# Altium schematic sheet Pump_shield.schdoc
size A4; Organization: ECAM; Revision: 0; SheetNumber: 1; SheetTotal: 1
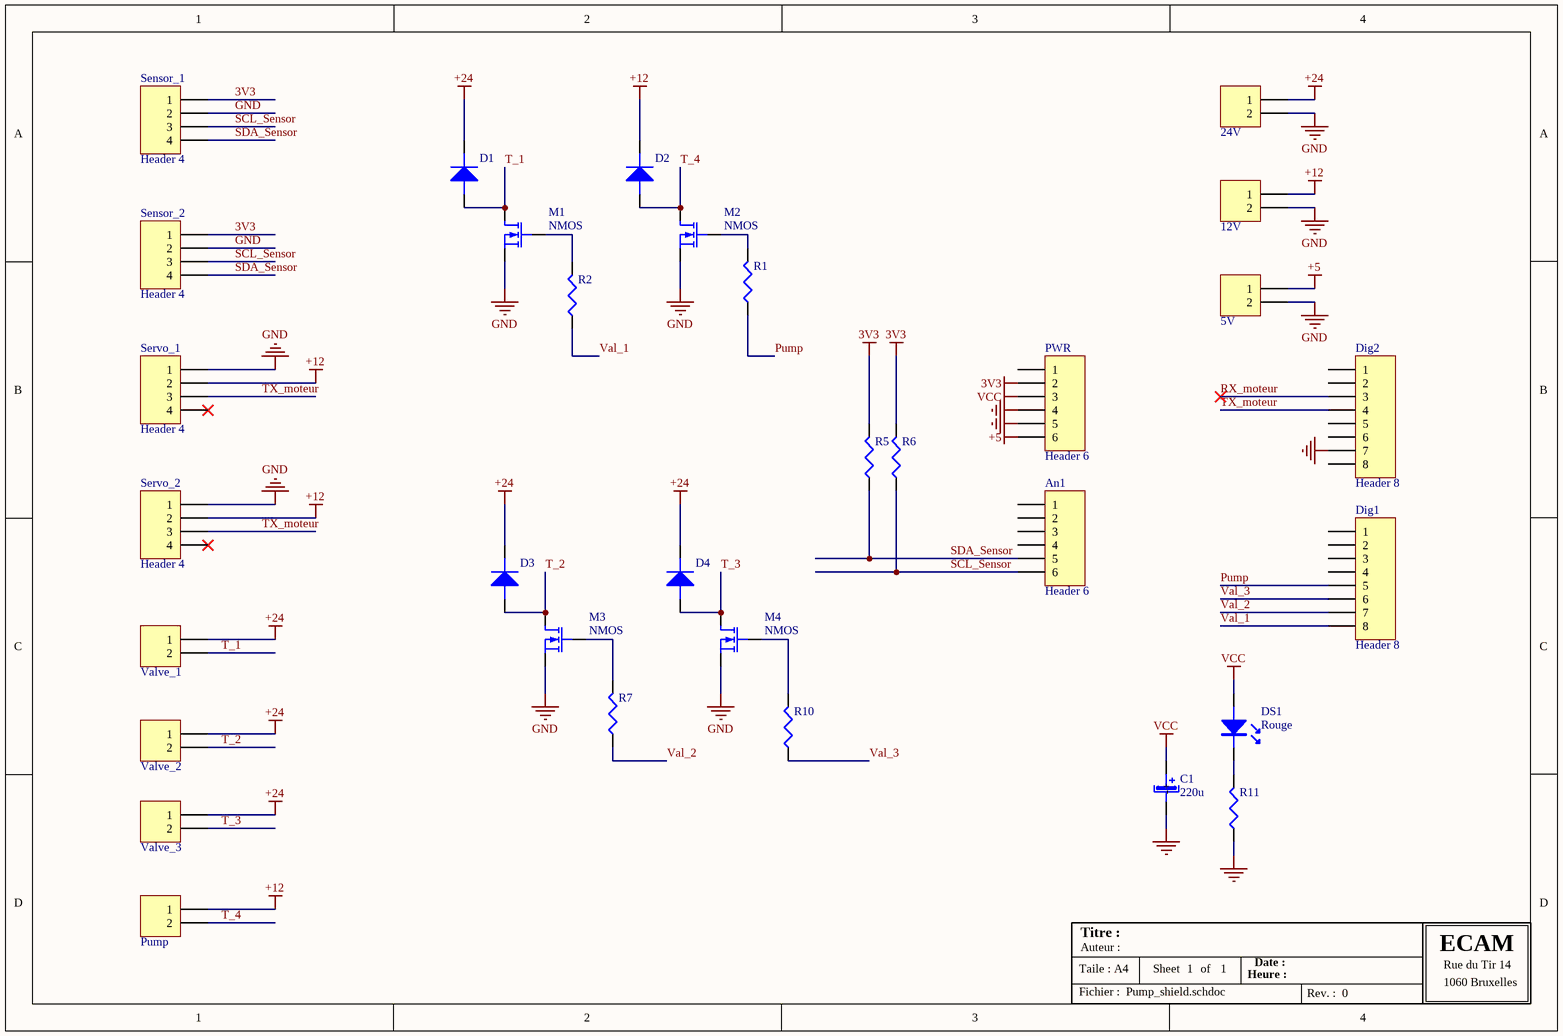
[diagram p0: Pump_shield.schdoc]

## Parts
5V  Connecteur 2  [Header_2]  (value not drawn)
12V  Connecteur 2  [Header_2]  (value not drawn)
24V  Connecteur 2  [Header_2]  (value not drawn)
An1  Header 6  [HDR1X6]
C1  value 220u  [CAPAE0810X700N]  (hidden comment: Cap_220u)
D1  Diode  [DIO7.1-3.9x1.9]  (value not drawn)
D2  Diode  [DIO7.1-3.9x1.9]  (value not drawn)
D3  Diode  [DIO7.1-3.9x1.9]  (value not drawn)
D4  Diode  [DIO7.1-3.9x1.9]  (value not drawn)
Dig1  Header 8  [HDR1X8]
Dig2  Header 8  [HDR1X8]
DS1  Color: Rouge  [LED 0.1]  (hidden comment: LED)
M1  value NMOS  [TO-92bis_MOS-N]  (hidden comment: MOSFET-N)
M2  value NMOS  [TO-220_MOS-N]  (hidden comment: MOSFET-N)
M3  value NMOS  [TO-92bis_MOS-N]  (hidden comment: MOSFET-N)
M4  value NMOS  [TO-92bis_MOS-N]  (hidden comment: MOSFET-N)
Pump  Connecteur 2  [Header_2]  (value not drawn)
PWR  Header 6  [HDR1X6]
R1  Résistance  [AXIAL-0.4]  (value not drawn)
R2  Résistance  [AXIAL-0.4]  (value not drawn)
R5  Résistance  [AXIAL-0.4]  (value not drawn)
R6  Résistance  [AXIAL-0.4]  (value not drawn)
R7  Résistance  [AXIAL-0.4]  (value not drawn)
R10  Résistance  [AXIAL-0.4]  (value not drawn)
R11  Résistance  [AXIAL-0.4]  (value not drawn)
Sensor_1  Header 4  [Header_4]
Sensor_2  Header 4  [Header_4]
Servo_1  Header 4  [Header_4]
Servo_2  Header 4  [Header_4]
Valve_1  Connecteur 2  [Header_2]  (value not drawn)
Valve_2  Connecteur 2  [Header_2]  (value not drawn)
Valve_3  Connecteur 2  [Header_2]  (value not drawn)

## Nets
3V3: PWR.2 R5.2 R6.2 Sensor_1.1 Sensor_2.1
+5: 5V.1 PWR.6
+12: 12V.1 D2.2(K) Pump.1 Servo_1.2 Servo_2.2
+24: 24V.1 D1.2(K) D3.2(K) D4.2(K) Valve_1.1 Valve_2.1 Valve_3.1
GND: 5V.2 12V.2 24V.2 C1.NEG(-) Dig2.7 M1.S M2.S M3.S M4.S PWR.4 PWR.5 R11.1 Sensor_1.2 Sensor_2.2 Servo_1.1 Servo_2.1
VCC: C1.POS(+) DS1.1(A) PWR.3
Pump: Dig1.5 R1.1
RX_moteur: Dig2.3
SCL_Sensor: An1.6 R6.1 Sensor_1.3 Sensor_2.3
SDA_Sensor: An1.5 R5.1 Sensor_1.4 Sensor_2.4
T_1: D1.1(A) M1.D Valve_1.2
T_2: D3.1(A) M3.D Valve_2.2
T_3: D4.1(A) M4.D Valve_3.2
T_4: D2.1(A) M2.D Pump.2
TX_moteur: Dig2.4 Servo_1.3 Servo_2.3
Val_1: Dig1.8 R2.1
Val_2: Dig1.7 R7.1
Val_3: Dig1.6 R10.1
NetDS1_2: DS1.2(K) R11.2
NetM1_G: M1.G R2.2
NetM2_G: M2.G R1.2
NetM3_G: M3.G R7.2
NetM4_G: M4.G R10.2

Not connected (* = marked no-connect by the designer): An1 1 2 3 4; Dig1 1 2 3 4; Dig2 1 2 5 6 8; PWR 1; Servo_1 4*; Servo_2 4*

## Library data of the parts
5V 12V 24V Pump Valve_1-Valve_3 = Connecteur 2: Header 2
An1 PWR = Header 6: Header, 6-Pin
C1 = Cap_220u: Condensateur polatisé; Type: Condensateur polarisé debout
D1-D4 = Diode: Type: Diode standard
Dig1 Dig2 = Header 8: Header, 8-Pin
M1-M4 = MOSFET-N: MOSFET
R1 R2 R5-R7 R10 R11 = Résistance: Résistance standard
Sensor_1 Sensor_2 Servo_1 Servo_2 = Header 4: Header, 4-Pin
